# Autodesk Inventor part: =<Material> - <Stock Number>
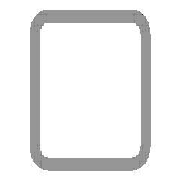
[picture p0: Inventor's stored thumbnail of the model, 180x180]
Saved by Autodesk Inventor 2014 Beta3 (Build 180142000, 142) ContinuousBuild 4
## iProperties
IsCustomPart: 1
_CCFamilyMember: 9
_CCFamilyDisplayName: ANSI AISC (Square) - Tube
_FrameMemberDoc: Frame Member File
_Version: 15.0.0
_GetPNFromCC: 1
Created: 2011-01
Part Number: =<Material> - <Stock Number>
Material: Steel, Mild
Description: Tube
Document SubType Name: Modeling
Standard: ANSI
Designer: Beta-8540w
Standards Organization: ANSI
Language: en-US
Size Designation: 3x3x3/16
Categories: <MemberInstance><Categories><Category DisplayName="Structural Shapes" InternalName="089c4875-fa83-4c05-b084-43b9cc11f5ed" Mnemonic="GRDR"><CategoryParameter Dis
Stock Number: 3x3x3/16
Density: 7.86 g/cm^3
Appearance: Steel
G_L: 28.000 in
G_W: 3.000 in
G_H: 3.000 in
Author: Beta-8540w
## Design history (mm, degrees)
node "Start plane"
node "End plane"
sketch "Sketch"
  geometry: L1 (-38.1, -28.575)-(-38.1, 28.575); L2 (-28.575, 38.1)-(28.575, 38.1); L3 (38.1, 28.575)-(38.1, -28.575); L4 (28.575, -38.1)-(-28.575, -38.1); L5 (-28.575, 33.337)-(28.575, 33.338); L6 (33.338, 28.575)-(33.338, -28.575); L7 (28.575, -33.337)-(-28.575, -33.338); L8 (-33.338, -28.575)-(-33.338, 28.575); L9 (0, 56.102)-(0, -56.102) reference; L10 (-56.102, 0)-(56.102, 0) reference; A1 r 9.525 centre (-28.575, -28.575) between (-38.1, -28.575) and (-28.575, -38.1); A2 r 9.525 centre (-28.575, 28.575) between (-28.575, 38.1) and (-38.1, 28.575); A3 r 9.525 centre (28.575, 28.575) between (38.1, 28.575) and (28.575, 38.1); A4 r 9.525 centre (28.575, -28.575) between (28.575, -38.1) and (38.1, -28.575); A5 r 4.763 centre (-28.575, 28.575) between (-28.575, 33.337) and (-33.338, 28.575); A6 r 4.763 centre (28.575, 28.575) between (33.338, 28.575) and (28.575, 33.338); A7 r 4.763 centre (28.575, -28.575) between (28.575, -33.337) and (33.338, -28.575); A8 r 4.763 centre (-28.575, -28.575) between (-33.338, -28.575) and (-28.575, -33.338)
  constraints: 16 end point, 16 point on circle, 8 centre point, 8 tangent, 4 parallel, 3 equal radius, 2 perpendicular, 7 other
  dimensions: "d10" = 76.2 distance between parallel lines of L2 L4 (= G_H); "d11" = 76.2 distance between parallel lines of L1 L3 (= G_W); "d12" = 4.7625 distance between parallel lines of L3 L6 (= G_T); "d15" = 38.1 distance between parallel lines of L2 L10 (= 0.5 x d10); "d16" = 38.1 distance between parallel lines of L9 L3 (= 0.5 x d11); "d17" = 9.525 radius of A1 (= G_IR)
extrude "Body" new body sketch "Sketch" stored distance "d3" = 711.2 (= G_L); taper "d4" = 0 deg
node "Driven Length"
  sketch "Sketch3"
    geometry: L1 (0, 0)-(10, 0) reference
    constraints: 2 end point, 1 horizontal
  workplane "Work Plane3"
  sketch "Sketch4"
    geometry: L1 (-2, 0)-(12, 0) reference; L2 (-2, 711.2)-(12, 711.2) reference
    dimensions: "d19" = 711.2 distance between parallel lines of L1 L2 (derived)
body "Solid1"
other parameters: "G_W" = 76.2 [user parameter; used in 1 equation term], "G_H" = 76.2 [user parameter; used in 1 equation term], "G_T" = 4.7625 [user parameter; used in 1 equation term], "G_IR" = 9.525 [user parameter; used in 1 equation term], "G_L" = 711.2 (= d19) [user parameter; used in 1 equation term], "G_OFFSET_START" = 0 [user parameter; used in 1 equation term], "G_OFFSET_END" = 0 [user parameter; used in 1 equation term], "d13" = 0 (computed from G_OFFSET_START), "d14" = 711.2 (= G_OFFSET_END + B_L), "B_L" = 711.2 [user parameter; used in 1 equation term], "d18" = 90 deg
